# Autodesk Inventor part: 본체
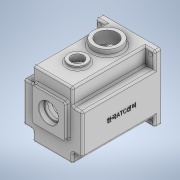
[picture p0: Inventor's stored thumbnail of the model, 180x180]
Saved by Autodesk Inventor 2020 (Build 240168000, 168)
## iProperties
Created: 2022-01
Part Number: 본체
Material: 일반
Document SubType Name: Modeling
Designer: user
Density: 1 g/cm^3
Appearance: 기본값
Author: user
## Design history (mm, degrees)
sketch "스케치1"
  geometry: L1 (-49, -55)-(49, -55); L2 (49, -55)-(49, 55); L3 (49, 55)-(-49, 55); L4 (-49, 55)-(-49, -55); L5 (-49, -55)-(49, 55); L6 (49, -55)-(-49, 55); 1 further point
  constraints: 12 end point, 2 midpoint, 2 parallel, 1 horizontal, 1 perpendicular
  dimensions: "d0" = 98 distance of L2.end L3.end; "d1" = 110 distance of L1.end L2.end
extrude "돌출1" new body sketch "스케치1" distance "d2" = 130; taper "d3" = 0 deg
sketch "스케치2"
  geometry: L1 (82, -130)-(98, -130); L2 (98, -130)-(98, -10); L3 (98, -10)-(82, -10); L4 (82, -10)-(82, -130); L5 (82, -130)-(98, -10); L6 (98, -130)-(82, -10); L7 (0, -130)-(16, -130); L8 (16, -130)-(16, -10); L9 (16, -10)-(0, -10); L10 (0, -10)-(0, -130); L11 (0, -130)-(16, -10); L12 (16, -130)-(0, -10); L13 (98, 0)-(0, 0) reference; 5 further points
  constraints: 24 end point, 4 midpoint, 4 parallel, 2 coincident, 2 horizontal, 2 perpendicular, 1 point on line
  dimensions: "d4" = 16 distance of L8.end L9.end; "d5" = 16 distance of L2.end L3.end; "d6" = 10 distance between parallel lines of L3 L13
extrude "돌출2" cut sketch "스케치2" distance "d7" = 27; taper "d8" = 0 deg
sketch "스케치3"
  geometry: L1 (16, 10)-(16, 130) reference; L2 (82, 130)-(82, 10) reference; L3 (0, 10)-(16, 10); L4 (16, 10)-(16, 130); L5 (16, 130)-(0, 130); L6 (0, 130)-(0, 10); L7 (0, 10)-(16, 130); L8 (16, 10)-(0, 130); L9 (82, 10)-(98, 10); L10 (98, 10)-(98, 130); L11 (98, 130)-(82, 130); L12 (82, 130)-(82, 10); L13 (82, 10)-(98, 130); L14 (98, 10)-(82, 130); L15 (0, 0)-(98, 0) reference; 9 further points
  constraints: 24 end point, 4 midpoint, 4 parallel, 2 coincident, 2 horizontal, 2 perpendicular, 1 point on line
  dimensions: "d9" = 16 distance between parallel lines of L4 L6; "d10" = 16 distance between parallel lines of L10 L12; "d11" = 10 distance between parallel lines of L15 L3; "d12" = 10 distance between parallel lines of L15 L9
extrude "돌출3" cut sketch "스케치3" distance "d13" = 17; taper "d14" = 0 deg
sketch "스케치5"
  geometry: L1 (49, -55)-(-49, -55) reference; L2 (23, 30.143)-(23, 45); L3 (23, 45)-(-23, 45); L4 (-23, 45)-(-23, 30.143); A1 r 42 centre (0, -5) between (-23, 30.143) and (23, 30.143); 1 further point
  constraints: 6 end point, 2 point on circle, 1 centre point, 1 parallel, 1 vertical alignment
  dimensions: "d23" = 84 diameter of A1; "d24" = 50 distance from line of L1 A1.centre; "d25" = 46 distance between parallel lines of L2 L4; "d26" = 50 distance from line of L3 A1.centre
extrude "돌출6" cut sketch "스케치5" distance "d27" = 121; taper "d28" = 0 deg
sketch "스케치7"
  geometry: L1 (-23, 45)-(23, 45) reference; L2 (-23, 30.143)-(-23, 45) reference; L3 (23, 45)-(23, 30.143) reference; L4 (26, 31.729)-(26, 48); L5 (26, 48)-(-26, 48); L6 (-26, 48)-(-26, 31.729); A1 r 42 centre (0, -5) between (-23, 30.143) and (23, 30.143) reference; A2 r 45 centre (0, -5) between (-26, 31.729) and (26, 31.729); 1 further point
  constraints: 6 end point, 2 point on circle, 1 centre point, 3 other
  dimensions: "d29" = 3 distance between parallel lines of L3 L4
extrude "돌출7" cut sketch "스케치7" distance "d30" = 9; taper "d31" = 0 deg
sketch "스케치8"
  geometry: L1 (98, 0)-(0, 0) reference; L2 (82, -10)-(98, -10) reference; L3 (98, 0)-(98, -10) reference; L4 (98, 0)-(0, 0) reference; L5 (0, 0)-(0, -10) reference; L6 (0, -10)-(16, -10) reference; L7 (16, -10)-(16, -130) reference; L8 (82, -130)-(16, -130) reference; L9 (82, -130)-(82, -10) reference; C1 r 22.5 at (49, -40); C2 r 15 at (49, -89); 2 further points
  constraints: 2 centre point, 2 vertical alignment, 1 midpoint
  dimensions: "d32" = 40 distance of point (49, 0) C1.centre; "d33" = 49 distance of C2.centre C1.centre; "d34" = 30 diameter of C2; "d35" = 45 diameter of C1
  node "투영된 루프1"
extrude "돌출8" join sketch "스케치8" distance "d36" = 10; taper "d37" = 0 deg
extrude "돌출9" join sketch "스케치8" distance "d38" = 5; taper "d39" = 0 deg
sketch "스케치9"
  geometry: C1 r 15 at (0, 0) reference; 2 further points
  constraints: 1 coincident
hole "구멍1" sketch "스케치9" at (0, 0) diameter "d40" = 20; stored, may be unused: countersink angle "d44" = 90 deg, drill point angle "d46" = 0 deg; dims "d41" = 10, "d42" = 4, "d43" = 2, "d45" = 55
sketch "스케치10"
  geometry: C1 r 10 at (23, -32) reference; C2 r 15 at (23, -32); 1 further point
  constraints: 1 centre point, 1 coincident
  dimensions: "d47" = 30 diameter of C2
extrude "돌출10" cut sketch "스케치10" distance "d48" = 5; taper "d49" = 0 deg
sketch "스케치11"
  geometry: C1 r 22.5 at (0, 0) reference; 2 further points
  constraints: 1 coincident
hole "구멍2" sketch "스케치11" at (0, 0) diameter "d50" = 33.376; stored, may be unused: countersink angle "d54" = 90 deg, drill point angle "d56" = 0 deg; dims "d51" = 52, "d52" = 4, "d53" = 2, "d55" = 55
sketch "스케치12"
  geometry: L1 (33, -55)-(-33, -55) reference; C1 r 15 at (0, -25); C2 r 21 at (0, 6); 3 further points
  constraints: 2 centre point
  dimensions: "d57" = 30 distance from line of L1 C1.centre; "d58" = 31 distance of C2.centre C1.centre; "d59" = 30 diameter of C1; "d60" = 42 diameter of C2
extrude "돌출11" join sketch "스케치12" distance "d61" = 7; taper "d62" = 0 deg
sketch "스케치13"
  geometry: C1 r 17.5 at (0, 6); A1 r 15 centre (0, -25) between (-8.978, -12.984) and (8.978, -12.984) reference; A2 r 21 centre (0, 6) between (8.978, -12.984) and (-8.978, -12.984) reference; 1 further point
  constraints: 1 centre point, 1 coincident
  dimensions: "d63" = 35 diameter of C1
extrude "돌출12" cut sketch "스케치13" distance "d64" = 10; taper "d65" = 0 deg
sketch "스케치17"
  geometry: L1 (-27, -21)-(27, -21); L2 (27, -21)-(27, 33); L3 (27, 33)-(-27, 33); L4 (-27, 33)-(-27, -21); L5 (-27, -21)-(27, 33); L6 (27, -21)-(-27, 33); C1 r 17.5 at (0, 6) reference; 2 further points
  constraints: 12 end point, 2 midpoint, 2 parallel, 1 horizontal, 1 perpendicular
  dimensions: "d66" = 54 distance of L2.end L3.end; "d67" = 54 distance of L1.end L2.end; "d68" = 27 distance from line of C1.centre L3
extrude "돌출13" join sketch "스케치17" distance "d69" = 7; taper "d70" = 0 deg
sketch "스케치19"
  geometry: C1 r 17.5 at (0, 6) reference; 1 further point
hole "구멍3" sketch "스케치19" at (0, 6) diameter "d71" = 28; stored, may be unused: countersink angle "d75" = 90 deg, drill point angle "d77" = 0 deg; dims "d72" = 52, "d73" = 32, "d74" = 8.3, "d76" = 10
sketch "스케치20"
  geometry: C1 r 17.5 at (0, 6) reference; A1 r 15 centre (0, -25) between (-8.978, -12.984) and (8.978, -12.984) reference; A2 r 21 centre (0, 6) between (8.978, -12.984) and (-8.978, -12.984) reference; 1 further point
hole "구멍4" sketch "스케치20" at (0, -25) diameter "d78" = 19; stored, may be unused: countersink angle "d82" = 90 deg, drill point angle "d84" = 0 deg; dims "d79" = 52, "d80" = 22, "d81" = 7, "d83" = 10
sketch "스케치22"
  geometry: L1 (-23, 30.143)-(-23, 45) reference; L2 (23, 45)-(23, 30.143) reference; L3 (-23, 45)-(23, 45) reference; L4 (-35.778, -1.006)-(-41.81, -1.006); L5 (35.778, -1.006)-(41.81, -1.006); L6 (-35.778, -8.994)-(-41.776, -9.328); L7 (35.778, -8.994)-(41.776, -9.328); C1 r 9.5 at (0, -25) reference; C2 r 14 at (0, 6) reference; A1 r 21 centre (0, 6) between (8.978, -12.984) and (-8.978, -12.984) reference; A2 r 15 centre (0, -25) between (-8.978, -12.984) and (8.978, -12.984) reference; A3 r 42 centre (0, -5) between (-23, 30.143) and (23, 30.143) reference; A4 r 36 centre (0, -5) between (-36, -5) and (36, -5); A5 r 4 centre (-36, -5) between (-35.778, -1.006) and (-35.778, -8.994); A6 r 4 centre (36, -5) between (35.778, -1.006) and (35.778, -8.994); A7 r 42 centre (0, -5) between (-23, 30.143) and (23, 30.143) reference; 4 further points
  constraints: 14 point on circle, 8 end point, 3 centre point, 2 horizontal alignment, 2 tangent, 1 coincident, 1 horizontal, 1 point on line
  dimensions: "d86" = 72 diameter of A4; "d87" = 8 diameter of A5; "d88" = 8 diameter of A6
extrude "돌출14" join sketch "스케치22" stored distance "d89" = 105; taper "d90" = 0 deg
sketch "스케치23"
  geometry: A1 r 4 centre (-36, -5) between (-35.778, -8.994) and (-36.222, -1.006) reference; 2 further points
  constraints: 1 coincident
hole "구멍5" sketch "스케치23" at (-36, -5) diameter "d91" = 3.242; stored, may be unused: countersink angle "d95" = 90 deg, drill point angle "d97" = 118 deg; dims "d92" = 7, "d93" = 22, "d94" = 7, "d96" = 9
sketch "스케치24"
  geometry: A1 r 4 centre (36, -5) between (35.778, -1.006) and (35.778, -8.994) reference; 2 further points
  constraints: 1 coincident
hole "구멍6" sketch "스케치24" at (36, -5) diameter "d98" = 3.242; stored, may be unused: countersink angle "d102" = 90 deg, drill point angle "d104" = 118 deg; dims "d99" = 7, "d100" = 22, "d101" = 7, "d103" = 9
sketch "스케치25"
  geometry: L1 (-49, -55)-(-49, 55) reference; L2 (-49, 55)-(49, 55) reference; 2 further points
  dimensions: "d105" = 7 distance from line of L1 point (-42, 48); "d106" = 7 distance from line of L2 point (-42, 48)
hole "구멍7" sketch "스케치25" at (-42, 48) diameter "d107" = 7; stored, may be unused: countersink angle "d111" = 90 deg, drill point angle "d113" = 0 deg; dims "d108" = 7, "d109" = 22, "d110" = 7, "d112" = 9
sketch "스케치26"
  geometry: 1 further point
sketch "스케치27"
  geometry: 1 further point
fillet "모깎기1" dims "d114" = 0.3
chamfer "모따기1" distance "d115" = 1; stored, may be unused: second distance "d116" = 2, angle "d117" = 45 deg
chamfer "모따기2" distance "d118" = 0.8; stored, may be unused: second distance "d119" = 2, angle "d120" = 30 deg
fillet "모깎기3" dims "d122" = 3
fillet "모깎기4" dims "d123" = 3
fillet "모깎기5" dims "d127" = 3
fillet "모깎기6" dims "d128" = 3
fillet "모깎기7" dims "d129" = 3
fillet "모깎기8" dims "d130" = 3
fillet "모깎기9" dims "d131" = 3
fillet "모깎기10" dims "d132" = 3
fillet "모깎기11" dims "d133" = 3
fillet "모깎기12" dims "d134" = 3
sketch "스케치28"
  geometry: L1 (-10, 80)-(-127, 80) reference; L2 (-130, 104)-(-130, 83) reference; 2 further points
  constraints: 1 other
  dimensions: "d135" = 33 distance from line of point (-65, 47) L1; "d136" = 65 distance from line of L2 point (-65, 47)
feature "엠보싱1" sketch "스케치28" dims "d4" = 16, "d5" = 16, "d6" = 10, "d137" = 0.5, "d138" = 0
fillet "모깎기13" dims "d139" = 6
fillet "모깎기14" dims "d140" = 6
fillet "모깎기15" dims "d141" = 3
chamfer "모따기4" distance "d142" = 1; stored, may be unused: second distance "d143" = 2, angle "d144" = 30 deg
chamfer "모따기5" distance "d145" = 1; stored, may be unused: second distance "d146" = 2, angle "d147" = 30 deg
chamfer "모따기6" distance "d148" = 1; stored, may be unused: second distance "d149" = 2, angle "d150" = 30 deg
chamfer "모따기7" distance "d151" = 1; stored, may be unused: second distance "d152" = 2, angle "d153" = 30 deg
fillet "모깎기16" dims "d154" = 3
node "솔리드1"
mirror "미러1"
mirror "미러2"
node "투영된 루프2"
node "투영된 루프4"
node "투영된 루프5"
node "투영된 루프6"
node "투영된 루프8"
node "투영된 루프9"
feature "A9D066F2-1C7D-4E18-AEED-F7BC21143FA4" dims "d40" = 20, "d41" = 10, "d42" = 4, "d43" = 2, "d44" = 90 deg, "d45" = 55, "d46" = 0
